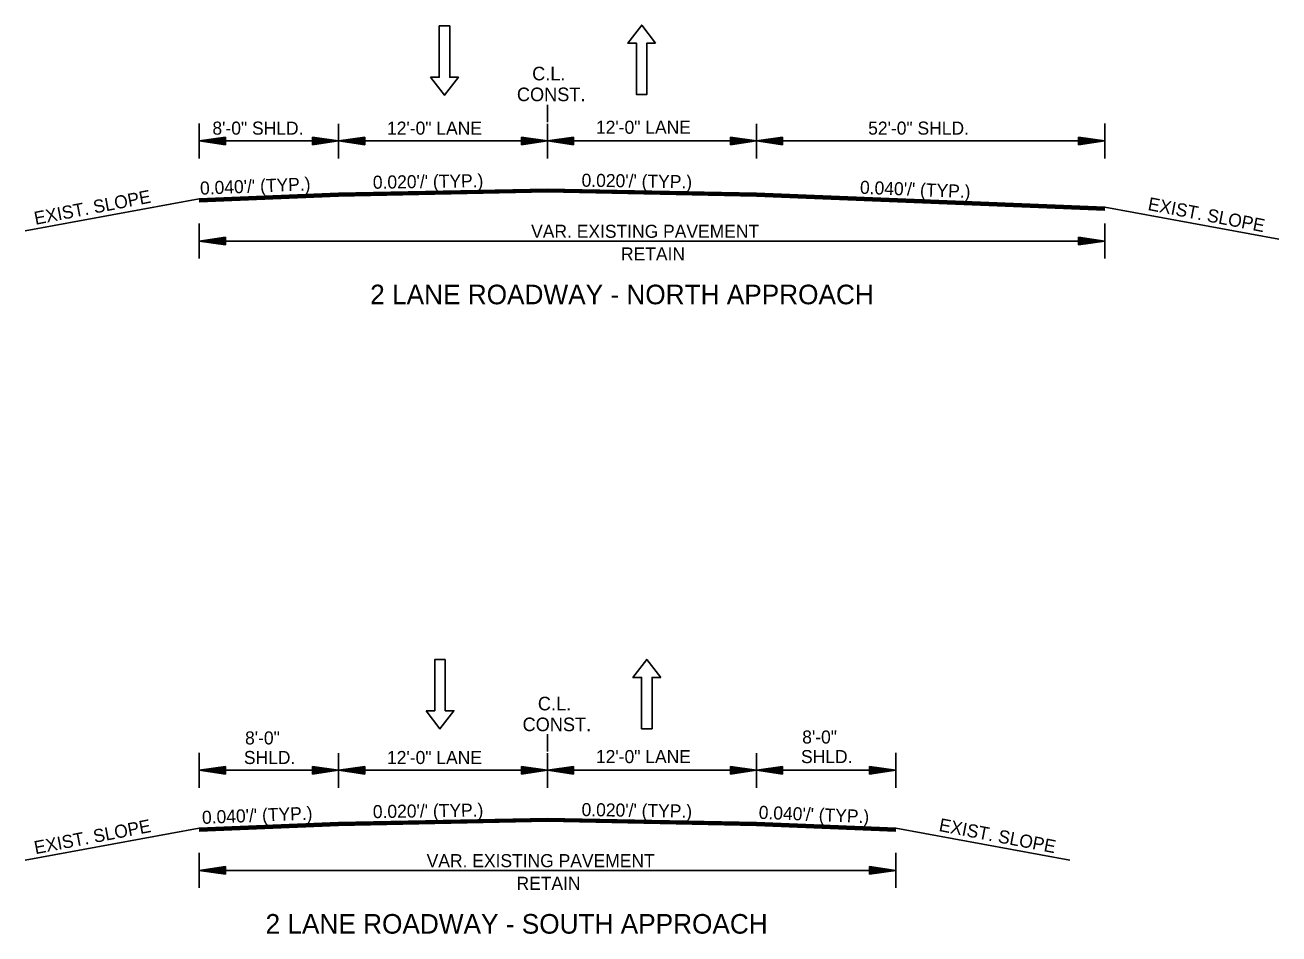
# Model space of a CAD drawing. Extents: x 545241 to 1930787, y -1971772 to 596640.
# Drawn here: x 546883 to 547604, y -1957103 to -1956581 of the extents above; entities that cross this region are included whole.
import ezdxf

# ---------------------------------------------------------------- set-up
doc = ezdxf.new("R2010")
doc.units = 0
doc.layers.add('R_Border', color=7, linetype='Continuous')
doc.layers.add('R_Draft', color=7, linetype='Continuous')

msp = doc.modelspace()

# ---------------------------------------------------------------- linework, layer by layer
at = {"layer": 'R_Border'}
for p, q in [((547063.55, -1956677.93), (546983.55, -1956681.13)), ((547063.55, -1956678.23), (546983.55, -1956681.43)), ((547063.55, -1956678.53), (546983.55, -1956681.73)), ((547063.55, -1956678.83), (546983.55, -1956682.03)), ((547063.55, -1956679.13), (546983.55, -1956682.33)), ((547063.55, -1956679.43), (546983.55, -1956682.63)), ((547063.55, -1956679.6), (546983.55, -1956682.8)), ((547303.55, -1956677.93), (547503.55, -1956685.93)), ((547303.55, -1956678.23), (547503.55, -1956686.23)), ((547303.55, -1956678.53), (547503.55, -1956686.53)), ((547303.55, -1956678.83), (547503.55, -1956686.83)), ((547303.55, -1956679.13), (547503.55, -1956687.13)), ((547303.55, -1956679.43), (547503.55, -1956687.43)), ((547303.55, -1956679.6), (547503.55, -1956687.6)), ((547063.55, -1957039.33), (546983.55, -1957042.53)), ((547063.55, -1957039.62), (546983.55, -1957042.82)), ((547063.55, -1957039.92), (546983.55, -1957043.12)), ((547063.55, -1957040.23), (546983.55, -1957043.43)), ((547063.55, -1957040.53), (546983.55, -1957043.73)), ((547063.55, -1957040.83), (546983.55, -1957044.03)), ((547063.55, -1957041), (546983.55, -1957044.2)), ((547303.55, -1957039.33), (547383.55, -1957042.53)), ((547303.55, -1957039.63), (547383.55, -1957042.83)), ((547303.55, -1957039.93), (547383.55, -1957043.13)), ((547303.55, -1957040.23), (547383.55, -1957043.43)), ((547303.55, -1957040.53), (547383.55, -1957043.73)), ((547303.55, -1957040.83), (547383.55, -1957044.03)), ((547303.55, -1957041), (547383.55, -1957044.2))]:
    msp.add_line(p, q, dxfattribs=at)
for points in [[(547116.38, -1956611.34), (547124.4, -1956621.72), (547132.38, -1956611.33), (547127.38, -1956611.33), (547127.35, -1956581.91), (547121.35, -1956581.91), (547121.38, -1956611.34)], [(547245.64, -1956591.77), (547237.64, -1956581.39), (547229.64, -1956591.77), (547234.64, -1956591.77), (547234.64, -1956621.2), (547240.64, -1956621.2), (547240.64, -1956591.77)], [(547113.77, -1956975.16), (547121.78, -1956985.53), (547129.77, -1956975.14), (547124.77, -1956975.15), (547124.74, -1956945.72), (547118.74, -1956945.73), (547118.77, -1956975.15)], [(547248.57, -1956956.02), (547240.57, -1956945.64), (547232.57, -1956956.02), (547237.57, -1956956.02), (547237.57, -1956985.45), (547243.57, -1956985.45), (547243.57, -1956956.02)]]:
    msp.add_lwpolyline(points, close=True, dxfattribs=at)
at = {"layer": 'R_Draft'}
for p, q in [((547183.55, -1956637.15), (547183.55, -1956627.15)), ((546983.55, -1956657.92), (546983.55, -1956637.92)), ((547063.55, -1956657.92), (547063.55, -1956638.03)), ((547183.55, -1956657.92), (547183.55, -1956638.03)), ((547303.55, -1956657.92), (547303.55, -1956638.03)), ((547503.55, -1956657.92), (547503.55, -1956637.92)), ((546998.55, -1956645.67), (546983.55, -1956647.92)), ((546998.55, -1956646.04), (546986.05, -1956647.92)), ((546998.55, -1956646.43), (546988.63, -1956647.92)), ((546998.55, -1956646.8), (546991.13, -1956647.92)), ((546998.55, -1956645.67), (546998.55, -1956650.17)), ((547048.55, -1956645.67), (547063.55, -1956647.92)), ((547048.55, -1956650.17), (547048.55, -1956645.67)), ((547048.55, -1956646.04), (547061.04, -1956647.92)), ((547048.55, -1956646.43), (547058.46, -1956647.92)), ((547048.55, -1956646.8), (547055.97, -1956647.92)), ((547078.55, -1956645.67), (547063.55, -1956647.92)), ((547078.55, -1956646.04), (547066.05, -1956647.92)), ((547078.55, -1956646.43), (547068.63, -1956647.92)), ((547078.55, -1956646.8), (547071.13, -1956647.92)), ((547078.55, -1956650.17), (547078.55, -1956645.67)), ((547168.55, -1956645.67), (547183.55, -1956647.92)), ((547168.55, -1956645.67), (547168.55, -1956650.17)), ((547168.55, -1956646.04), (547181.04, -1956647.92)), ((547168.55, -1956646.43), (547178.46, -1956647.92)), ((547168.55, -1956646.8), (547175.97, -1956647.92)), ((547198.55, -1956645.67), (547183.55, -1956647.92)), ((547198.55, -1956646.04), (547186.05, -1956647.92)), ((547198.55, -1956646.43), (547188.63, -1956647.92)), ((547198.55, -1956646.8), (547191.13, -1956647.92)), ((547198.55, -1956645.67), (547198.55, -1956650.17)), ((547288.55, -1956645.67), (547303.55, -1956647.92)), ((547288.55, -1956650.17), (547288.55, -1956645.67)), ((547288.55, -1956646.04), (547301.04, -1956647.92)), ((547288.55, -1956646.43), (547298.46, -1956647.92)), ((547288.55, -1956646.8), (547295.97, -1956647.92)), ((547318.55, -1956645.67), (547303.55, -1956647.92)), ((547318.55, -1956646.04), (547306.05, -1956647.92)), ((547318.55, -1956646.43), (547308.63, -1956647.92)), ((547318.55, -1956646.8), (547311.13, -1956647.92)), ((547318.55, -1956650.17), (547318.55, -1956645.67)), ((547488.55, -1956645.67), (547503.55, -1956647.92)), ((547488.55, -1956645.67), (547488.55, -1956650.17)), ((547488.55, -1956646.04), (547501.04, -1956647.92)), ((547488.55, -1956646.43), (547498.46, -1956647.92)), ((547488.55, -1956646.8), (547495.97, -1956647.92)), ((547063.55, -1956647.92), (546983.55, -1956647.92)), ((546998.55, -1956650.17), (546983.55, -1956647.92)), ((546998.55, -1956649.79), (546986.05, -1956647.92)), ((546998.55, -1956649.41), (546988.63, -1956647.92)), ((546998.55, -1956649.04), (546991.13, -1956647.92)), ((546998.55, -1956647.19), (546993.67, -1956647.92)), ((546998.55, -1956648.65), (546993.67, -1956647.92)), ((546998.55, -1956647.57), (546996.18, -1956647.92)), ((546998.55, -1956648.27), (546996.18, -1956647.92)), ((547048.55, -1956647.18), (547053.42, -1956647.92)), ((547048.55, -1956647.57), (547050.92, -1956647.92)), ((547048.55, -1956650.17), (547063.55, -1956647.92)), ((547048.55, -1956648.65), (547053.42, -1956647.92)), ((547048.55, -1956649.41), (547058.46, -1956647.92)), ((547048.55, -1956649.79), (547061.04, -1956647.92)), ((547048.55, -1956649.04), (547055.97, -1956647.92)), ((547048.55, -1956648.27), (547050.92, -1956647.92)), ((547078.55, -1956650.17), (547063.55, -1956647.92)), ((547063.55, -1956647.92), (547183.55, -1956647.92)), ((547078.55, -1956649.79), (547066.05, -1956647.92)), ((547078.55, -1956649.41), (547068.63, -1956647.92)), ((547078.55, -1956649.04), (547071.13, -1956647.92)), ((547078.55, -1956647.18), (547073.67, -1956647.92)), ((547078.55, -1956648.65), (547073.67, -1956647.92)), ((547078.55, -1956647.57), (547076.18, -1956647.92)), ((547078.55, -1956648.27), (547076.18, -1956647.92)), ((547168.55, -1956647.19), (547173.42, -1956647.92)), ((547168.55, -1956647.57), (547170.92, -1956647.92)), ((547168.55, -1956650.17), (547183.55, -1956647.92)), ((547168.55, -1956648.65), (547173.42, -1956647.92)), ((547168.55, -1956649.41), (547178.46, -1956647.92)), ((547168.55, -1956649.79), (547181.04, -1956647.92)), ((547168.55, -1956649.04), (547175.97, -1956647.92)), ((547168.55, -1956648.27), (547170.92, -1956647.92)), ((547303.55, -1956647.92), (547183.55, -1956647.92)), ((547198.55, -1956650.17), (547183.55, -1956647.92)), ((547198.55, -1956649.79), (547186.05, -1956647.92)), ((547198.55, -1956649.41), (547188.63, -1956647.92)), ((547198.55, -1956649.04), (547191.13, -1956647.92)), ((547198.55, -1956647.19), (547193.67, -1956647.92)), ((547198.55, -1956648.65), (547193.67, -1956647.92)), ((547198.55, -1956647.57), (547196.18, -1956647.92)), ((547198.55, -1956648.27), (547196.18, -1956647.92)), ((547288.55, -1956647.18), (547293.42, -1956647.92)), ((547288.55, -1956647.57), (547290.92, -1956647.92)), ((547288.55, -1956650.17), (547303.55, -1956647.92)), ((547288.55, -1956648.65), (547293.42, -1956647.92)), ((547288.55, -1956649.41), (547298.46, -1956647.92)), ((547288.55, -1956649.79), (547301.04, -1956647.92)), ((547288.55, -1956649.04), (547295.97, -1956647.92)), ((547288.55, -1956648.27), (547290.92, -1956647.92)), ((547303.55, -1956647.92), (547503.55, -1956647.92)), ((547318.55, -1956650.17), (547303.55, -1956647.92)), ((547318.55, -1956649.79), (547306.05, -1956647.92)), ((547318.55, -1956649.41), (547308.63, -1956647.92)), ((547318.55, -1956649.04), (547311.13, -1956647.92)), ((547318.55, -1956647.18), (547313.67, -1956647.92)), ((547318.55, -1956648.65), (547313.67, -1956647.92)), ((547318.55, -1956647.57), (547316.18, -1956647.92)), ((547318.55, -1956648.27), (547316.18, -1956647.92)), ((547488.55, -1956647.19), (547493.42, -1956647.92)), ((547488.55, -1956647.57), (547490.92, -1956647.92)), ((547488.55, -1956650.17), (547503.55, -1956647.92)), ((547488.55, -1956648.65), (547493.42, -1956647.92)), ((547488.55, -1956649.41), (547498.46, -1956647.92)), ((547488.55, -1956649.79), (547501.04, -1956647.92)), ((547488.55, -1956649.04), (547495.97, -1956647.92)), ((547488.55, -1956648.27), (547490.92, -1956647.92)), ((547183.55, -1956675.53), (547063.55, -1956677.93)), ((547183.54, -1956675.83), (547063.55, -1956678.23)), ((547183.54, -1956675.83), (547303.55, -1956678.23)), ((547183.55, -1956675.53), (547303.55, -1956677.93)), ((546983.55, -1956681.13), (546883.48, -1956699.5)), ((547183.55, -1956676.13), (547063.55, -1956678.53)), ((547183.57, -1956676.43), (547063.55, -1956678.83)), ((547183.57, -1956676.73), (547063.55, -1956679.13)), ((547183.58, -1956677.03), (547063.55, -1956679.43)), ((547183.58, -1956677.2), (547063.55, -1956679.6)), ((547183.51, -1956677.2), (547303.55, -1956679.6)), ((547183.52, -1956676.73), (547303.55, -1956679.13)), ((547183.52, -1956677.03), (547303.55, -1956679.43)), ((547183.53, -1956676.43), (547303.55, -1956678.83)), ((547183.54, -1956676.13), (547303.55, -1956678.53)), ((547503.55, -1956685.93), (547603.62, -1956704.3)), ((546983.55, -1956695.38), (546983.55, -1956715.38)), ((547503.55, -1956695.38), (547503.55, -1956715.38)), ((546998.55, -1956703.13), (546983.55, -1956705.38)), ((546998.55, -1956703.51), (546986.05, -1956705.38)), ((546998.55, -1956703.89), (546988.63, -1956705.38)), ((546998.55, -1956704.27), (546991.13, -1956705.38)), ((546998.55, -1956704.65), (546993.67, -1956705.38)), ((546998.55, -1956707.63), (546998.55, -1956703.13)), ((547488.55, -1956703.13), (547503.55, -1956705.38)), ((547488.55, -1956703.13), (547488.55, -1956707.63)), ((547488.55, -1956703.51), (547501.04, -1956705.38)), ((547488.55, -1956703.89), (547498.46, -1956705.38)), ((547488.55, -1956704.27), (547495.97, -1956705.38)), ((546983.55, -1956705.38), (547503.55, -1956705.38)), ((546998.55, -1956707.63), (546983.55, -1956705.38)), ((546998.55, -1956707.26), (546986.05, -1956705.38)), ((546998.55, -1956706.88), (546988.63, -1956705.38)), ((546998.55, -1956706.5), (546991.13, -1956705.38)), ((546998.55, -1956706.11), (546993.67, -1956705.38)), ((546998.55, -1956705.03), (546996.18, -1956705.38)), ((546998.55, -1956705.74), (546996.18, -1956705.38)), ((547488.55, -1956704.66), (547493.42, -1956705.38)), ((547488.55, -1956705.03), (547490.92, -1956705.38)), ((547488.55, -1956707.63), (547503.55, -1956705.38)), ((547488.55, -1956706.12), (547493.42, -1956705.38)), ((547488.55, -1956706.88), (547498.46, -1956705.38)), ((547488.55, -1956707.26), (547501.04, -1956705.38)), ((547488.55, -1956706.5), (547495.97, -1956705.38)), ((547488.55, -1956705.74), (547490.92, -1956705.38)), ((547183.55, -1956998.54), (547183.55, -1956988.54)), ((546983.55, -1957019.32), (546983.55, -1956999.32)), ((547063.55, -1957019.32), (547063.55, -1956999.43)), ((547183.55, -1957019.32), (547183.55, -1956999.43)), ((547303.55, -1957019.32), (547303.55, -1956999.43)), ((547383.55, -1957019.32), (547383.55, -1956999.32)), ((546998.55, -1957007.07), (546983.55, -1957009.32)), ((546998.55, -1957007.07), (546998.55, -1957011.57)), ((547048.55, -1957007.07), (547063.55, -1957009.32)), ((547048.55, -1957011.57), (547048.55, -1957007.07)), ((547078.55, -1957007.07), (547063.55, -1957009.32)), ((547078.55, -1957011.57), (547078.55, -1957007.07)), ((547168.55, -1957007.07), (547183.55, -1957009.32)), ((547168.55, -1957007.07), (547168.55, -1957011.57)), ((547198.55, -1957007.07), (547183.55, -1957009.32)), ((547198.55, -1957007.07), (547198.55, -1957011.57)), ((547288.55, -1957007.07), (547303.55, -1957009.32)), ((547288.55, -1957011.57), (547288.55, -1957007.07)), ((547318.55, -1957007.07), (547303.55, -1957009.32)), ((547318.55, -1957011.57), (547318.55, -1957007.07)), ((547368.55, -1957007.07), (547383.55, -1957009.32)), ((547368.55, -1957007.07), (547368.55, -1957011.57)), ((547063.55, -1957009.32), (546983.55, -1957009.32)), ((546998.55, -1957011.57), (546983.55, -1957009.32)), ((546998.55, -1957007.44), (546986.05, -1957009.32)), ((546998.55, -1957011.19), (546986.05, -1957009.32)), ((546998.55, -1957007.83), (546988.63, -1957009.32)), ((546998.55, -1957010.81), (546988.63, -1957009.32)), ((546998.55, -1957008.2), (546991.13, -1957009.32)), ((546998.55, -1957010.44), (546991.13, -1957009.32)), ((546998.55, -1957008.59), (546993.67, -1957009.32)), ((546998.55, -1957010.05), (546993.67, -1957009.32)), ((546998.55, -1957008.97), (546996.18, -1957009.32)), ((546998.55, -1957009.67), (546996.18, -1957009.32)), ((547048.55, -1957007.44), (547061.04, -1957009.32)), ((547048.55, -1957007.83), (547058.46, -1957009.32)), ((547048.55, -1957008.2), (547055.97, -1957009.32)), ((547048.55, -1957008.58), (547053.42, -1957009.32)), ((547048.55, -1957008.97), (547050.92, -1957009.32)), ((547048.55, -1957011.57), (547063.55, -1957009.32)), ((547048.55, -1957010.05), (547053.42, -1957009.32)), ((547048.55, -1957010.81), (547058.46, -1957009.32)), ((547048.55, -1957011.19), (547061.04, -1957009.32)), ((547048.55, -1957010.44), (547055.97, -1957009.32)), ((547048.55, -1957009.67), (547050.92, -1957009.32)), ((547078.55, -1957011.57), (547063.55, -1957009.32)), ((547063.55, -1957009.32), (547183.55, -1957009.32)), ((547078.55, -1957007.44), (547066.05, -1957009.32)), ((547078.55, -1957011.19), (547066.05, -1957009.32)), ((547078.55, -1957007.83), (547068.63, -1957009.32)), ((547078.55, -1957010.81), (547068.63, -1957009.32)), ((547078.55, -1957008.2), (547071.13, -1957009.32)), ((547078.55, -1957010.44), (547071.13, -1957009.32)), ((547078.55, -1957008.58), (547073.67, -1957009.32)), ((547078.55, -1957010.05), (547073.67, -1957009.32)), ((547078.55, -1957008.97), (547076.18, -1957009.32)), ((547078.55, -1957009.67), (547076.18, -1957009.32)), ((547168.55, -1957007.44), (547181.04, -1957009.32)), ((547168.55, -1957007.83), (547178.46, -1957009.32)), ((547168.55, -1957008.2), (547175.97, -1957009.32)), ((547168.55, -1957008.59), (547173.42, -1957009.32)), ((547168.55, -1957008.97), (547170.92, -1957009.32)), ((547168.55, -1957011.57), (547183.55, -1957009.32)), ((547168.55, -1957010.05), (547173.42, -1957009.32)), ((547168.55, -1957010.81), (547178.46, -1957009.32)), ((547168.55, -1957011.19), (547181.04, -1957009.32)), ((547168.55, -1957010.44), (547175.97, -1957009.32)), ((547168.55, -1957009.67), (547170.92, -1957009.32)), ((547303.55, -1957009.32), (547183.55, -1957009.32)), ((547198.55, -1957011.57), (547183.55, -1957009.32)), ((547198.55, -1957007.44), (547186.05, -1957009.32)), ((547198.55, -1957011.19), (547186.05, -1957009.32)), ((547198.55, -1957007.83), (547188.63, -1957009.32)), ((547198.55, -1957010.81), (547188.63, -1957009.32)), ((547198.55, -1957008.2), (547191.13, -1957009.32)), ((547198.55, -1957010.44), (547191.13, -1957009.32)), ((547198.55, -1957008.59), (547193.67, -1957009.32)), ((547198.55, -1957010.05), (547193.67, -1957009.32)), ((547198.55, -1957008.97), (547196.18, -1957009.32)), ((547198.55, -1957009.67), (547196.18, -1957009.32)), ((547288.55, -1957007.44), (547301.04, -1957009.32)), ((547288.55, -1957007.83), (547298.46, -1957009.32)), ((547288.55, -1957008.2), (547295.97, -1957009.32)), ((547288.55, -1957008.58), (547293.42, -1957009.32)), ((547288.55, -1957008.97), (547290.92, -1957009.32)), ((547288.55, -1957011.57), (547303.55, -1957009.32)), ((547288.55, -1957010.05), (547293.42, -1957009.32)), ((547288.55, -1957010.81), (547298.46, -1957009.32)), ((547288.55, -1957011.19), (547301.04, -1957009.32)), ((547288.55, -1957010.44), (547295.97, -1957009.32)), ((547288.55, -1957009.67), (547290.92, -1957009.32)), ((547303.55, -1957009.32), (547383.55, -1957009.32)), ((547318.55, -1957011.57), (547303.55, -1957009.32)), ((547318.55, -1957007.44), (547306.05, -1957009.32)), ((547318.55, -1957011.19), (547306.05, -1957009.32)), ((547318.55, -1957007.83), (547308.63, -1957009.32)), ((547318.55, -1957010.81), (547308.63, -1957009.32)), ((547318.55, -1957008.2), (547311.13, -1957009.32)), ((547318.55, -1957010.44), (547311.13, -1957009.32)), ((547318.55, -1957008.58), (547313.67, -1957009.32)), ((547318.55, -1957010.05), (547313.67, -1957009.32)), ((547318.55, -1957008.97), (547316.18, -1957009.32)), ((547318.55, -1957009.67), (547316.18, -1957009.32)), ((547368.55, -1957007.44), (547381.04, -1957009.32)), ((547368.55, -1957007.83), (547378.46, -1957009.32)), ((547368.55, -1957008.2), (547375.97, -1957009.32)), ((547368.55, -1957008.59), (547373.42, -1957009.32)), ((547368.55, -1957008.97), (547370.92, -1957009.32)), ((547368.55, -1957011.57), (547383.55, -1957009.32)), ((547368.55, -1957010.05), (547373.42, -1957009.32)), ((547368.55, -1957010.81), (547378.46, -1957009.32)), ((547368.55, -1957011.19), (547381.04, -1957009.32)), ((547368.55, -1957010.44), (547375.97, -1957009.32)), ((547368.55, -1957009.67), (547370.92, -1957009.32)), ((546983.55, -1957042.53), (546883.48, -1957060.9)), ((547183.55, -1957036.93), (547063.55, -1957039.33)), ((547183.54, -1957037.23), (547063.55, -1957039.63)), ((547183.55, -1957037.53), (547063.55, -1957039.93)), ((547183.57, -1957037.83), (547063.55, -1957040.23)), ((547183.57, -1957038.12), (547063.55, -1957040.53)), ((547183.58, -1957038.42), (547063.55, -1957040.83)), ((547183.58, -1957038.59), (547063.55, -1957041)), ((547183.51, -1957038.59), (547303.55, -1957041)), ((547183.52, -1957038.12), (547303.55, -1957040.53)), ((547183.52, -1957038.42), (547303.55, -1957040.83)), ((547183.53, -1957037.83), (547303.55, -1957040.23)), ((547183.54, -1957037.23), (547303.55, -1957039.63)), ((547183.54, -1957037.53), (547303.55, -1957039.93)), ((547183.55, -1957036.93), (547303.55, -1957039.33)), ((547383.55, -1957042.53), (547483.62, -1957060.9)), ((546983.55, -1957056.78), (546983.55, -1957076.78)), ((547383.55, -1957056.78), (547383.55, -1957076.78)), ((546998.55, -1957064.53), (546983.55, -1957066.78)), ((546998.55, -1957069.03), (546998.55, -1957064.53)), ((547368.55, -1957064.53), (547383.55, -1957066.78)), ((547368.55, -1957064.53), (547368.55, -1957069.03)), ((546983.55, -1957066.78), (547383.55, -1957066.78)), ((546998.55, -1957069.03), (546983.55, -1957066.78)), ((546998.55, -1957064.91), (546986.05, -1957066.78)), ((546998.55, -1957068.66), (546986.05, -1957066.78)), ((546998.55, -1957065.29), (546988.63, -1957066.78)), ((546998.55, -1957068.28), (546988.63, -1957066.78)), ((546998.55, -1957065.67), (546991.13, -1957066.78)), ((546998.55, -1957067.9), (546991.13, -1957066.78)), ((546998.55, -1957066.05), (546993.67, -1957066.78)), ((546998.55, -1957067.51), (546993.67, -1957066.78)), ((546998.55, -1957066.43), (546996.18, -1957066.78)), ((546998.55, -1957067.14), (546996.18, -1957066.78)), ((547368.55, -1957064.91), (547381.04, -1957066.78)), ((547368.55, -1957065.29), (547378.46, -1957066.78)), ((547368.55, -1957065.67), (547375.97, -1957066.78)), ((547368.55, -1957066.06), (547373.42, -1957066.78)), ((547368.55, -1957066.43), (547370.92, -1957066.78)), ((547368.55, -1957069.03), (547383.55, -1957066.78)), ((547368.55, -1957067.52), (547373.42, -1957066.78)), ((547368.55, -1957068.28), (547378.46, -1957066.78)), ((547368.55, -1957068.66), (547381.04, -1957066.78)), ((547368.55, -1957067.9), (547375.97, -1957066.78)), ((547368.55, -1957067.14), (547370.92, -1957066.78))]:
    msp.add_line(p, q, dxfattribs=at)

# ---------------------------------------------------------------- texts
for s, height, p in [('C.L.', 7.8, (547174.73, -1956613.12)), ('CONST.', 7.8, (547165.95, -1956625.08)), ('8\'-0" SHLD.', 7.5, (546991.07, -1956644.31)), ('12\'-0" LANE', 7.5, (547091.36, -1956644.31)), ('12\'-0" LANE', 7.5, (547211.36, -1956643.79)), ('52\'-0" SHLD.', 7.5, (547367.7, -1956644.31)), ('VAR. EXISTING PAVEMENT', 7.5, (547174.13, -1956703.55)), ('RETAIN', 7.5, (547225.74, -1956716.56)), ('2 LANE ROADWAY - NORTH APPROACH', 11.25, (547081.71, -1956741.7)), ('C.L.', 7.8, (547177.99, -1956974.88)), ('CONST.', 7.8, (547169.21, -1956986.84)), ('8\'-0"', 7.5, (547009.82, -1956994.46)), ('8\'-0"', 7.5, (547329.82, -1956993.94)), ('SHLD.', 7.5, (547009.14, -1957005.71)), ('12\'-0" LANE', 7.5, (547091.36, -1957005.71)), ('12\'-0" LANE', 7.5, (547211.36, -1957005.19)), ('SHLD.', 7.5, (547329.14, -1957005.19)), ('VAR. EXISTING PAVEMENT', 7.5, (547114.13, -1957064.95)), ('RETAIN', 7.5, (547165.74, -1957077.96)), ('2 LANE ROADWAY - SOUTH APPROACH', 11.25, (547021.62, -1957103.1))]:
    msp.add_text(s, height=height, dxfattribs=at).set_placement(p)
for s, rotation, p in [("0.040'/' (TYP.)", 2.29061, (546984.11, -1956678.8)), ("0.020'/' (TYP.)", 0.87191, (547083.27, -1956675.4)), ("0.020'/' (TYP.)", 359.12809, (547203.05, -1956674.18)), ("0.040'/' (TYP.)", 357.70939, (547362.89, -1956678.22)), ('EXIST. SLOPE', 10.88286, (546889.46, -1956696.12)), ('EXIST. SLOPE', 349.11714, (547527.93, -1956687.52)), ("0.020'/' (TYP.)", 0.87191, (547083.27, -1957036.8)), ("0.020'/' (TYP.)", 359.12809, (547203.05, -1957035.57)), ("0.040'/' (TYP.)", 2.29061, (546985.24, -1957040.13)), ("0.040'/' (TYP.)", 357.70939, (547304.72, -1957037.14)), ('EXIST. SLOPE', 10.88286, (546889.46, -1957057.52)), ('EXIST. SLOPE', 349.11714, (547407.93, -1957044.12))]:
    msp.add_text(s, height=7.5, rotation=rotation, dxfattribs=at).set_placement(p)

doc.saveas('drawing.dxf')
